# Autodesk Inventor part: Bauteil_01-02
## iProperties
Created: 2007-04
Part Number: Bauteil_01-02
Document SubType Name: Modeling
Designer: Sascha Fleischer
Author: Sascha Fleischer
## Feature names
1. Abgeleiteter Körper1 [Tagging]
